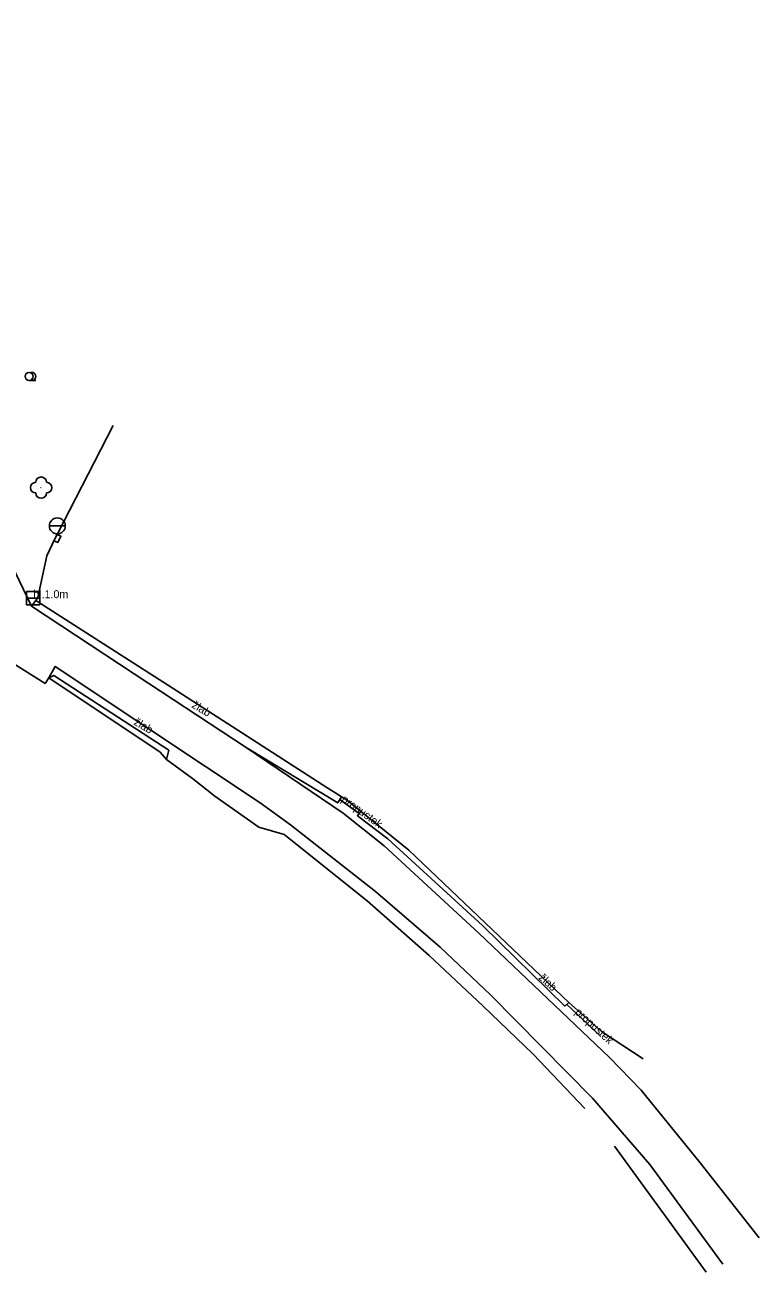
# Model space of a CAD drawing. Extents: x -747135 to -746147, y -1093269 to -1091735.
# Drawn here: x -746565.8 to -746497.1, y -1092986.9 to -1092870.1 of the extents above; entities that cross this region are included whole.
import ezdxf

# ---------------------------------------------------------------- set-up
doc = ezdxf.new("R2010")
doc.units = 0
for name, color, linetype in [('1016', 7, 'Continuous'), ('1029', 7, 'Continuous'), ('105', 7, 'Continuous'), ('23700', 7, 'Continuous'), ('305', 7, 'Continuous'), ('308', 7, 'Continuous'), ('316', 7, 'Continuous'), ('424', 7, 'Continuous'), ('803', 7, 'Continuous')]:
    doc.layers.add(name, color=color, linetype=linetype)

msp = doc.modelspace()

# ---------------------------------------------------------------- linework, layer by layer
at = {"layer": '1016'}
for points in [[(-746606.89, -1092870.07), (-746606.22, -1092872.2), (-746601.94, -1092884.53), (-746599.63, -1092891.7), (-746597.35, -1092899.83), (-746595.6, -1092905.67), (-746593.1, -1092909.17), (-746589.17, -1092912.29), (-746583.92, -1092914.8), (-746581.66, -1092915.56), (-746580.14, -1092915.86), (-746577.29, -1092915.71), (-746575.17, -1092914.86), (-746572.81, -1092912.41), (-746569.47, -1092912.97), (-746567.46, -1092919.83), (-746565.22, -1092924.53), (-746564.79, -1092924.01)], [(-746545.11, -1092937.76), (-746554.23, -1092931.78), (-746565.22, -1092924.53)], [(-746500.47, -1092986.18), (-746507.31, -1092976.85), (-746512.67, -1092970.64), (-746522.23, -1092960.96), (-746526.94, -1092956.47), (-746532.99, -1092951.27), (-746540.95, -1092945.03), (-746543.79, -1092942.97), (-746553.94, -1092936.2), (-746562.98, -1092930.17), (-746563.58, -1092931.24)], [(-746563.58, -1092931.24), (-746563.11, -1092931.01), (-746552.36, -1092938.03), (-746552.58, -1092938.9)], [(-746497.07, -1092983.72), (-746502.59, -1092976.7), (-746508.12, -1092969.87), (-746511.08, -1092966.82), (-746523.32, -1092955.18), (-746532.19, -1092946.97), (-746536.02, -1092943.93), (-746545.11, -1092937.76)], [(-746545.11, -1092937.76), (-746536.52, -1092942.96), (-746536.18, -1092942.4)], [(-746534.37, -1092943.75), (-746534.69, -1092944.17), (-746531.84, -1092946.32), (-746522.97, -1092954.45), (-746515.26, -1092962), (-746514.9, -1092961.67)]]:
    msp.add_lwpolyline(points, dxfattribs=at)
at = {"layer": '1029'}
msp.add_line((-746565.43, -1092903.38), (-746564.81, -1092903.38), dxfattribs=at)
msp.add_circle((-746565.43, -1092903), 0.375, dxfattribs=at)
msp.add_arc((-746565.18, -1092903), 0.375, 249.4944, 109.0474, dxfattribs=at)
at = {"layer": '23700'}
for points in [[(-746536.29, -1092942.66), (-746534.51, -1092943.96)], [(-746511.97, -1092964.75), (-746515.11, -1092961.83)]]:
    msp.add_lwpolyline(points, dxfattribs=at)
at = {"layer": '305'}
for points in [[(-746563.27, -1092918.74), (-746563.76, -1092919.81), (-746564.63, -1092923.71)], [(-746563.92, -1092931.77), (-746567.8, -1092929.34)], [(-746535.62, -1092942.75), (-746534.92, -1092943.3)], [(-746514.9, -1092961.67), (-746511.82, -1092964.37)]]:
    msp.add_lwpolyline(points, dxfattribs=at)
at = {"layer": '308'}
for points in [[(-746553.16, -1092938.21), (-746563.58, -1092931.24), (-746563.92, -1092931.77)], [(-746552.46, -1092931.89), (-746537.47, -1092941.59)]]:
    msp.add_lwpolyline(points, dxfattribs=at)
at = {"layer": '316'}
for p, q in [((-746562.04, -1092917.01), (-746563.54, -1092917.01)), ((-746564.42, -1092923.15), (-746565.68, -1092923.15)), ((-746565.68, -1092923.15), (-746565.68, -1092924.41)), ((-746564.42, -1092924.41), (-746564.42, -1092923.15)), ((-746565.68, -1092923.78), (-746564.43, -1092923.78)), ((-746565.68, -1092924.41), (-746564.42, -1092924.41))]:
    msp.add_line(p, q, dxfattribs=at)
msp.add_lwpolyline([(-746563.11, -1092918.4), (-746562.82, -1092917.8), (-746562.46, -1092917.97), (-746562.74, -1092918.56), (-746563.11, -1092918.4)], dxfattribs=at)
for start, end in [(0, 180), (180, 0)]:
    msp.add_arc((-746562.79, -1092917.01), 0.747, start, end, dxfattribs=at)
at = {"layer": '424'}
msp.add_circle((-746564.31, -1092913.42), 0.0005, dxfattribs=at)
for centre, start, end in [((-746564.81, -1092913.42), 90, 270), ((-746564.31, -1092912.92), 0, 180), ((-746563.81, -1092913.42), 270, 90), ((-746564.31, -1092913.92), 180, 360)]:
    msp.add_arc(centre, 0.5, start, end, dxfattribs=at)
at = {"layer": '803'}
for p, q in [((-746557.55, -1092907.59), (-746562.82, -1092917.8)), ((-746563.11, -1092918.4), (-746563.27, -1092918.74))]:
    msp.add_line(p, q, dxfattribs=at)
for points in [[(-746564.63, -1092923.71), (-746564.79, -1092924.01), (-746552.46, -1092931.89)], [(-746522.94, -1092961.98), (-746527.95, -1092957.26), (-746533.78, -1092952.15), (-746541.55, -1092945.93), (-746543.91, -1092945.22), (-746548.03, -1092942.32), (-746550.12, -1092940.66), (-746552.58, -1092938.9), (-746553.16, -1092938.21)], [(-746537.47, -1092941.59), (-746535.62, -1092942.75)], [(-746534.92, -1092943.3), (-746529.87, -1092947.38), (-746514.9, -1092961.67)], [(-746513.4, -1092971.58), (-746518.22, -1092966.5), (-746522.94, -1092961.98)], [(-746511.82, -1092964.37), (-746507.92, -1092966.93)], [(-746502.02, -1092986.92), (-746510.6, -1092975.13)]]:
    msp.add_lwpolyline(points, dxfattribs=at)

# ---------------------------------------------------------------- texts
at = {"layer": '105'}
msp.add_text('hl.1.0m', height=0.75, dxfattribs=at).set_placement((-746565.05, -1092923.78))
for s, rotation, p in [('žlab', 329.2343, (-746550.27, -1092933.98)), ('žlab', 329.2343, (-746555.7, -1092935.58)), ('propustek', 324.2298, (-746536.25, -1092942.78)), ('žlab', 317.5798, (-746517.77, -1092959.42)), ('propustek', 317.5798, (-746514.38, -1092962.66))]:
    msp.add_text(s, height=0.75, rotation=rotation, dxfattribs=at).set_placement(p)

doc.saveas('drawing.dxf')
